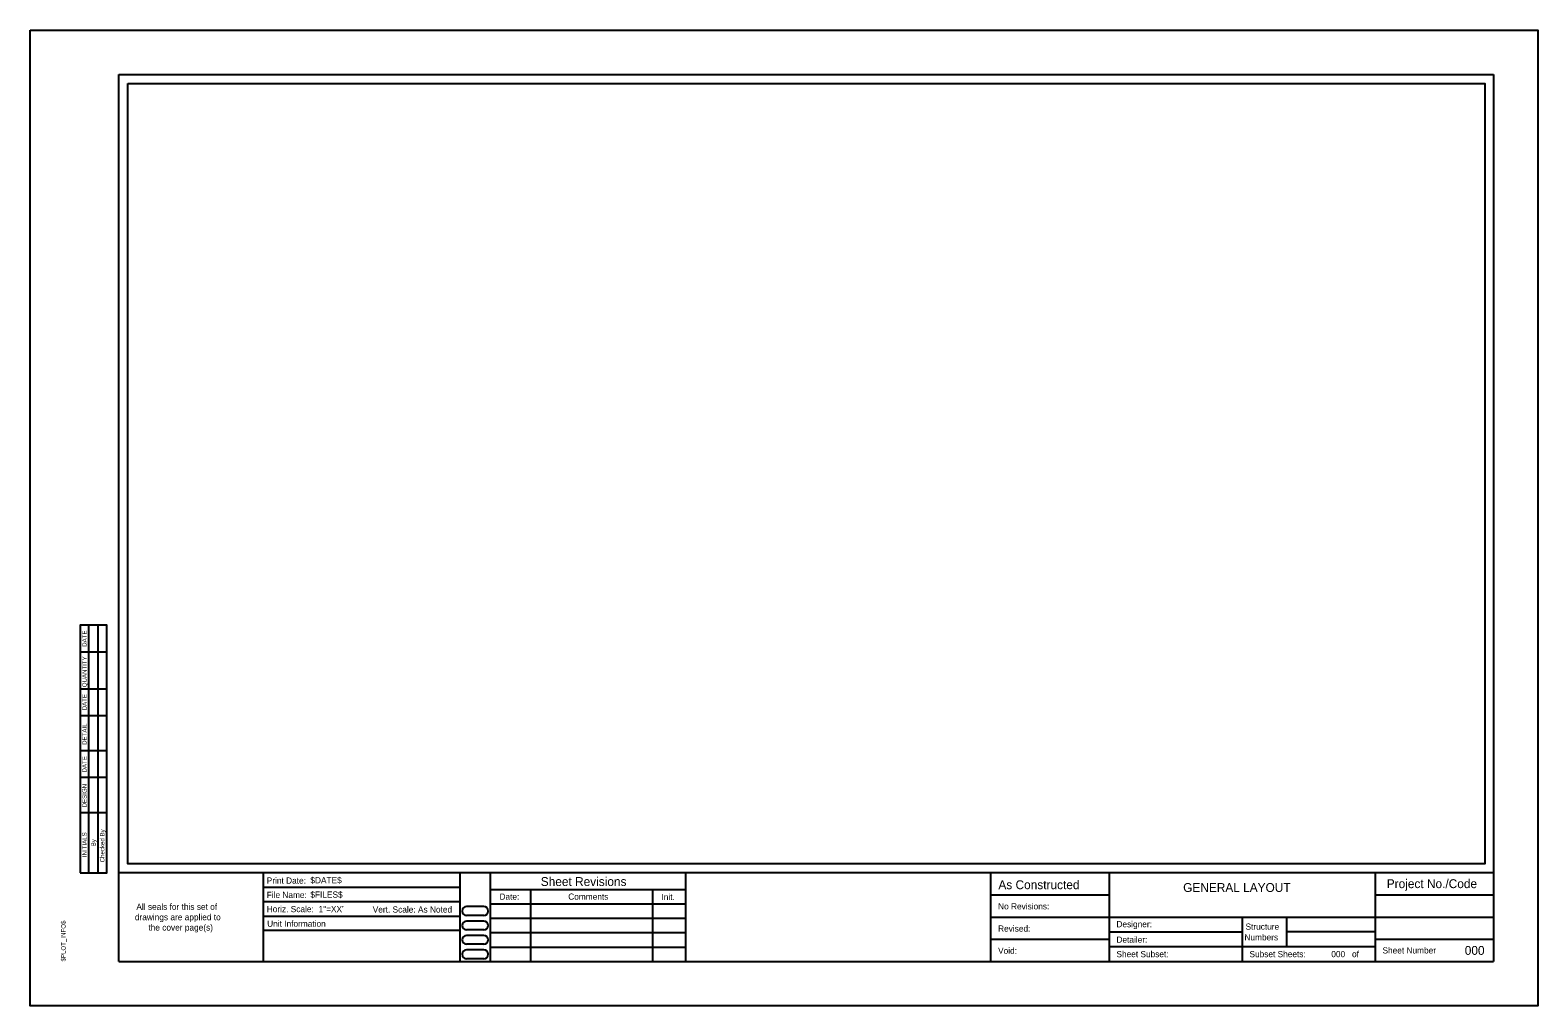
# Model space of a CAD drawing. Extents: x 0 to 1.42, y 0 to 0.92.
import ezdxf

# ---------------------------------------------------------------- set-up
doc = ezdxf.new("R2010")
doc.units = 0
for name, color, linetype in [('BRDG_OUTLINE', 7, 'Continuous'), ('DRAFT_Information-No Plot', 7, 'Continuous'), ('SHEET_Lines', 7, 'Continuous'), ('SHEET_Plot Boundary', 7, 'Continuous'), ('SHEET_Text-Border Info', 7, 'Continuous'), ('SHEET_Text-Sheet Number', 7, 'Continuous'), ('SHEET_Text-Titles', 7, 'Continuous')]:
    doc.layers.add(name, color=color, linetype=linetype)

msp = doc.modelspace()

# ---------------------------------------------------------------- linework, layer by layer
at = {"layer": 'BRDG_OUTLINE'}
for p, q in [((0.0552, 0.125), (0.0552, 0.3576)), ((0.0635, 0.3576), (0.0635, 0.125)), ((0.0469, 0.3326), (0.0719, 0.3326)), ((0.0469, 0.2979), (0.0719, 0.2979)), ((0.0469, 0.2729), (0.0719, 0.2729)), ((0.0719, 0.2396), (0.0469, 0.2396)), ((0.0719, 0.2146), (0.0469, 0.2146)), ((0.0719, 0.1813), (0.0469, 0.1813))]:
    msp.add_line(p, q, dxfattribs=at)
msp.add_lwpolyline([(0.0469, 0.125), (0.0719, 0.125), (0.0719, 0.3576), (0.0469, 0.3576)], close=True, dxfattribs=at)
at = {"layer": 'DRAFT_Information-No Plot'}
msp.add_line((0, 0), (0, 0), dxfattribs=at)
msp.add_lwpolyline([(0.0917, 0.8667), (1.3667, 0.8667), (1.3667, 0.1333), (0.0917, 0.1333)], close=True, dxfattribs=at)
at = {"layer": 'SHEET_Lines'}
for p, q in [((0.0833, 0.875), (1.375, 0.875)), ((0.0833, 0.0417), (0.0833, 0.875)), ((1.375, 0.875), (1.375, 0.0417)), ((1.375, 0.125), (0.0833, 0.125)), ((0.2188, 0.125), (0.2188, 0.0417)), ((0.4042, 0.0417), (0.4042, 0.125)), ((0.4324, 0.0417), (0.4324, 0.125)), ((0.616, 0.0417), (0.616, 0.125)), ((0.9028, 0.0417), (0.9028, 0.125)), ((1.0139, 0.125), (1.0139, 0.0417)), ((1.2639, 0.125), (1.2639, 0.0417)), ((0.2188, 0.1115), (0.4042, 0.1115)), ((0.4324, 0.1094), (0.616, 0.1094)), ((0.4706, 0.0417), (0.4706, 0.1094)), ((0.5852, 0.0417), (0.5852, 0.1094)), ((0.9028, 0.1042), (1.0139, 0.1042)), ((1.2639, 0.1042), (1.375, 0.1042)), ((0.2188, 0.098), (0.4042, 0.098)), ((0.4264, 0.0932), (0.41, 0.0932)), ((0.4324, 0.0958), (0.616, 0.0958)), ((0.2188, 0.0844), (0.4042, 0.0844)), ((0.4042, 0.0709), (0.2188, 0.0709)), ((0.4264, 0.085), (0.41, 0.085)), ((0.4264, 0.0796), (0.41, 0.0796)), ((0.4264, 0.0714), (0.41, 0.0714)), ((0.4324, 0.0823), (0.616, 0.0823)), ((0.9028, 0.0833), (1.375, 0.0833)), ((1.1389, 0.0833), (1.1389, 0.0417)), ((1.1806, 0.0833), (1.1806, 0.0556)), ((0.4264, 0.0661), (0.41, 0.0661)), ((0.4264, 0.0579), (0.41, 0.0579)), ((0.4324, 0.0688), (0.616, 0.0688)), ((0.9028, 0.0625), (1.0139, 0.0625)), ((1.0139, 0.0694), (1.1389, 0.0694)), ((1.2639, 0.0694), (1.1806, 0.0694)), ((1.2639, 0.0625), (1.375, 0.0625)), ((0.4264, 0.0525), (0.41, 0.0525)), ((0.4264, 0.0443), (0.41, 0.0443)), ((0.4324, 0.0552), (0.616, 0.0552)), ((1.0139, 0.0556), (1.2639, 0.0556)), ((0.0833, 0.0417), (1.375, 0.0417))]:
    msp.add_line(p, q, dxfattribs=at)
for centre, start, end in [((0.41, 0.0891), 90, 270), ((0.4264, 0.0891), 270, 90), ((0.41, 0.0755), 90, 270), ((0.4264, 0.0755), 270, 90), ((0.41, 0.062), 90, 270), ((0.4264, 0.062), 270, 90), ((0.41, 0.0484), 90, 270), ((0.4264, 0.0484), 270, 90)]:
    msp.add_arc(centre, 0.00409, start, end, dxfattribs=at)
at = {"layer": 'SHEET_Plot Boundary'}
msp.add_lwpolyline([(0, 0.9167), (1.4167, 0.9167), (1.4167, 0), (0, 0)], close=True, dxfattribs=at)

# ---------------------------------------------------------------- texts
at = {"layer": 'SHEET_Text-Border Info'}
for s, height, p in [('DATE', 0.00417, (0.0531, 0.3373)), ('QUANTITY', 0.00417, (0.0531, 0.2993)), ('DATE', 0.00417, (0.0531, 0.2776)), ('DETAIL', 0.00417, (0.0531, 0.2452)), ('DATE', 0.00417, (0.0531, 0.2192)), ('DESIGN', 0.00417, (0.0531, 0.1864)), ('INITIALS', 0.00417, (0.0531, 0.1397)), ('By', 0.00417, (0.0615, 0.1499)), ('Checked By', 0.00417, (0.0698, 0.1348)), ('$PLOT_INFO$', 0.004167, (0.0333, 0.0417))]:
    msp.add_text(s, height=height, rotation=90, dxfattribs=at).set_placement(p)
for s, height, p in [('Print Date:', 0.005833, (0.2223, 0.1148)), ('$DATE$', 0.00583, (0.2633, 0.1151)), ('File Name:', 0.00583, (0.2223, 0.1013)), ('$FILES$', 0.00583, (0.2633, 0.1016)), ('Date:', 0.00583, (0.441, 0.0997)), ('Comments', 0.00583, (0.5056, 0.0997)), ('Init.', 0.00583, (0.5932, 0.0994)), ('drawings are applied to', 0.005833, (0.0984, 0.0804)), ('All seals for this set of', 0.005833, (0.0998, 0.0902)), ('Horiz. Scale:', 0.005833, (0.2223, 0.088)), ('1"=XX\'', 0.00583, (0.271, 0.088)), ('Vert. Scale: As Noted', 0.005833, (0.3219, 0.0876)), ('No Revisions:', 0.005833, (0.9095, 0.0906)), ('the cover page(s)', 0.005833, (0.1111, 0.0707)), ('Unit Information', 0.005833, (0.2227, 0.0743)), ('Revised:', 0.00583, (0.9095, 0.0697)), ('Designer:', 0.00583, (1.0207, 0.0738)), ('Structure', 0.00583, (1.142, 0.0715)), ('Detailer:', 0.00583, (1.0207, 0.0593)), ('Numbers', 0.00583, (1.141, 0.0615)), ('Void:', 0.00583, (0.9095, 0.0489)), ('Sheet Subset:', 0.005833, (1.0207, 0.0457)), ('Subset Sheets:', 0.005833, (1.1457, 0.0457)), ('000', 0.00583, (1.2226, 0.0457)), (' of ', 0.00583, (1.2399, 0.0457)), ('Sheet Number', 0.005833, (1.2707, 0.0492))]:
    msp.add_text(s, height=height, dxfattribs=at).set_placement(p)
at = {"layer": 'SHEET_Text-Sheet Number'}
msp.add_text('000', height=0.00833, dxfattribs=at).set_placement((1.348, 0.0479))
at = {"layer": 'SHEET_Text-Titles'}
for s, p in [('Sheet Revisions', (0.4798, 0.1126)), ('As Constructed', (0.9098, 0.1096)), ('GENERAL LAYOUT', (1.0834, 0.107)), ('Project No./Code', (1.2747, 0.1106))]:
    msp.add_text(s, height=0.008333, dxfattribs=at).set_placement(p)

doc.saveas('drawing.dxf')
